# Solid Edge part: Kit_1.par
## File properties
Username: bmolnar
Dokumentum tartalom típus: 0
Author: bmolnar
Last saved by: bmolnar
Revision: 76
Sűrűség: 0,000 kg/m^3
Pontosság: 0,990
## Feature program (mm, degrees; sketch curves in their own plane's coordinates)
base feature "unnamed BaseFeature 1"
sketch for "unnamed Hole 1" plane through (-28.25, 28.25, 5) normal (0, 0, -1) x-axis (0, -1, 0)
  hole centre (0, 0) bore radius 3.3235
hole "unnamed Hole 1" through
sketch for "unnamed Hole 2" plane through (-28.25, 28.25, 5) normal (0, 0, -1) x-axis (0, -1, 0)
  hole centre (56.5, 0) bore radius 3.3235
hole "unnamed Hole 2" through
sketch for "unnamed Hole 3" plane through (-28.25, 28.25, 5) normal (0, 0, -1) x-axis (0, -1, 0)
  hole centre (0, -56.5) bore radius 3.3235
hole "unnamed Hole 3" through
sketch for "unnamed Hole 4" plane through (-28.25, 28.25, 5) normal (0, 0, -1) x-axis (0, -1, 0)
  hole centre (56.5, -56.5) bore radius 3.3235
hole "unnamed Hole 4" through
pattern "unnamed Pattern 1" of "unnamed Hole 1", "unnamed Hole 2", "unnamed Hole 3", "unnamed Hole 4"
thread "unnamed Thread 1"
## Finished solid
Body 1: solid body, 295 faces, 736 edges, 457 vertices.
  Faces by surface: plane 140, cylinder 74, swept 61, cone 11, torus 8, spline 1
  Edges by curve: line 431, circle 139, spline 126, ellipse 30, curve on surface 9, intersection 1
Bounding box of the edges (mm; curved faces can reach further): 77.000 x 77.000 x 13.750, from (-38.5, -38.5, 0) to (38.5, 38.5, 13.75).
Cylindrical faces by radius (mm): R0.2 x48, R0.2008 x2, R0.2009 x2, R0.402 x1, R0.4899 x1, R2 x1, R3.3235 x4, R4.283 x1, R4.9 x4, R5.15 x4, R5.25 x4, R6 x1, R17.0898 x1
Conical faces (half-angle, radius in mm at the cone's reference point): 0.5 deg R12 x4, 0.5 deg R13.5 x2, 45 deg R3.6735 x4, 45 deg R6.25 x1
Toroidal faces (ring radius, tube radius in mm): R4.7 r0.2 x8
Planar faces by outward normal: +x 12, +y 14, +z 1, -x 15, -y 13, -z 18, oblique 67
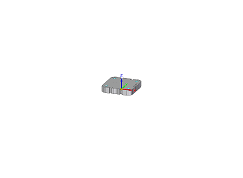
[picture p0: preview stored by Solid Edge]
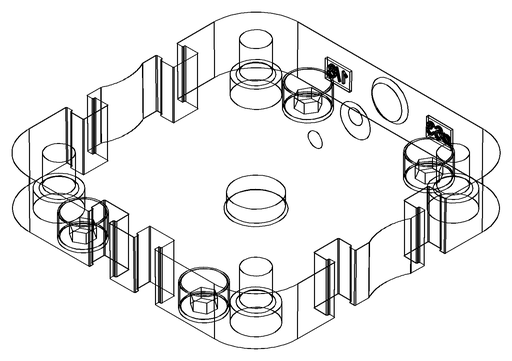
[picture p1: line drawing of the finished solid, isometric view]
